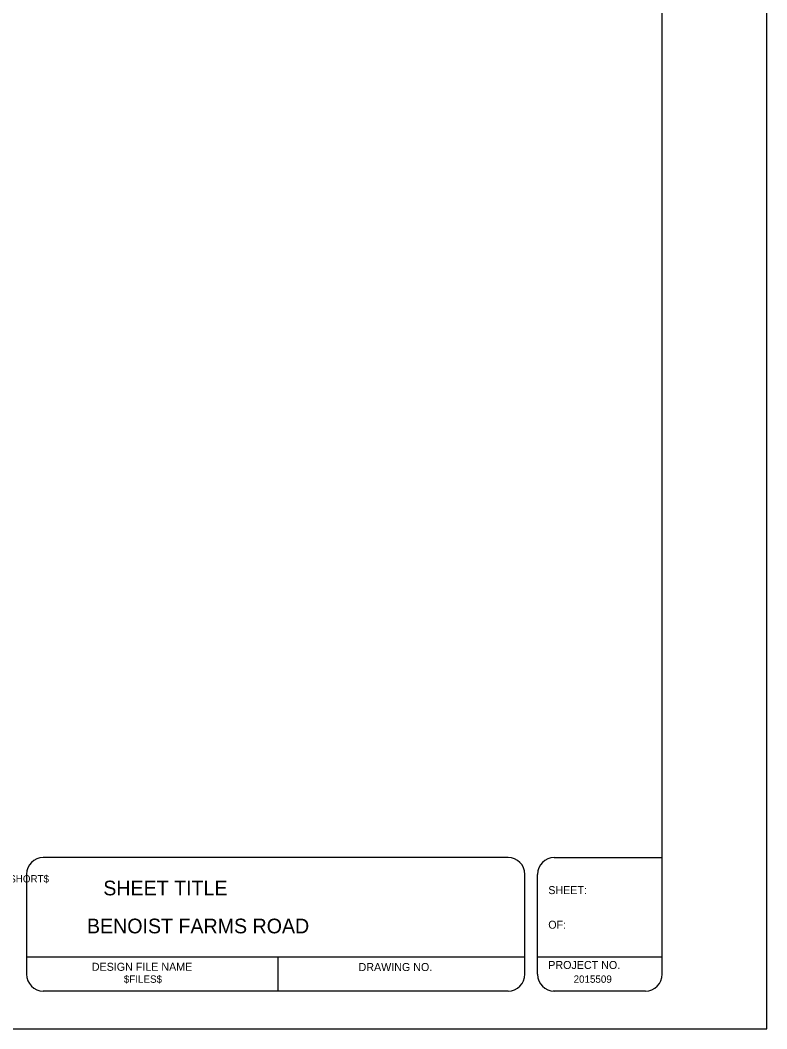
# Model space of a CAD drawing. Extents: x -0.7 to 16, y -0.9 to 9.7.
# Drawn here: x 12.02 to 15.95, y -0.9 to 4.4 of the extents above; entities that cross this region are included whole.
import ezdxf

# ---------------------------------------------------------------- set-up
doc = ezdxf.new("R2010")
doc.units = 0
for name, color, linetype in [('Default', 7, 'Continuous'), ('NonPlottingEle_dp', 7, 'Continuous'), ('PlotBorder_dp', 7, 'Continuous'), ('TextLabel', 7, 'Continuous'), ('TextMisc', 7, 'Continuous')]:
    doc.layers.add(name, color=color, linetype=linetype)

msp = doc.modelspace()

# ---------------------------------------------------------------- linework, layer by layer
at = {"layer": 'Default'}
for p, q in [((15.4, -0.6133), (15.4, 9.5065)), ((14.5898, 0), (12.146, 0)), ((14.8324, 0), (15.4, 0)), ((12.0578, -0.0882), (12.0578, -0.6131)), ((14.678, -0.6135), (14.678, -0.0884)), ((14.7442, -0.6135), (14.7442, -0.0884)), ((14.6769, -0.5241), (12.0568, -0.5241)), ((13.3801, -0.7005), (13.3801, -0.5241)), ((15.4, -0.5241), (14.7475, -0.5241)), ((14.5898, -0.7014), (12.146, -0.7014)), ((15.3118, -0.7015), (14.8271, -0.7015))]:
    msp.add_line(p, q, dxfattribs=at)
for centre, major_axis, start_param, end_param in [((12.146, -0.0882), (0, 0.0882), 0, 1.570796), ((14.5898, -0.0884), (0, 0.0882), 4.712389, 6.283185), ((14.8324, -0.0884), (0, -0.0882), 3.141593, 4.712389), ((12.146, -0.6131), (0, -0.0882), 4.712389, 6.283185), ((14.5898, -0.6131), (0, 0.0882), 3.141593, 4.712389), ((14.8324, -0.6135), (0, -0.0882), 4.712389, 6.283185), ((15.3118, -0.6133), (0, -0.0882), 0, 1.570796)]:
    msp.add_ellipse(centre, major_axis=major_axis, ratio=0.999927, start_param=start_param, end_param=end_param, dxfattribs=at)
at = {"layer": 'PlotBorder_dp'}
msp.add_lwpolyline([(-0.55, -0.9), (15.95, -0.9), (15.95, 9.7), (-0.55, 9.7)], close=True, dxfattribs=at)

# ---------------------------------------------------------------- texts
at = {"layer": 'Default'}
for s, height, p in [('SHEET:', 0.04207, (14.8009, -0.1922)), ('OF:', 0.04207, (14.8009, -0.374)), ('DESIGN FILE NAME', 0.042066, (12.4009, -0.5951)), ('DRAWING NO.', 0.042066, (13.8035, -0.5964)), ('PROJECT NO.', 0.042066, (14.8009, -0.5856)), ('$FILES$', 0.03855, (12.5694, -0.6581)), ('2015509', 0.03855, (14.9341, -0.6581))]:
    msp.add_text(s, height=height, dxfattribs=at).set_placement(p)
at = {"layer": 'NonPlottingEle_dp'}
msp.add_text('   BENOIST FARMS ROAD   ', height=0.077091, dxfattribs=at).set_placement((12.2895, -0.3982))
at = {"layer": 'TextLabel'}
msp.add_text('$SCALESHORT$', height=0.038546, dxfattribs=at).set_placement((11.7691, -0.1311))
at = {"layer": 'TextMisc'}
msp.add_text('      SHEET TITLE       ', height=0.077091, dxfattribs=at).set_placement((12.2895, -0.1987))

doc.saveas('drawing.dxf')
